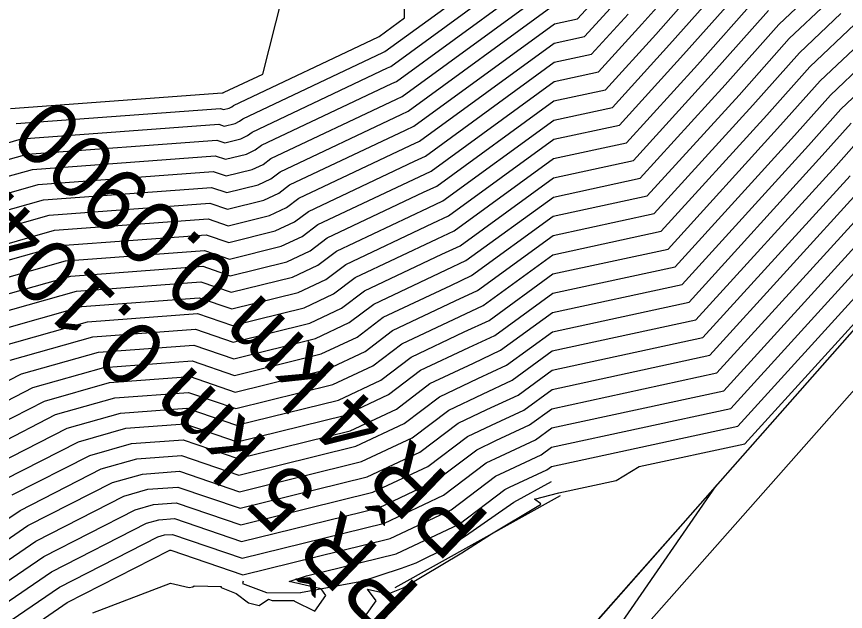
# Model space of a CAD drawing. Extents: x -549394 to -546608, y -1037055 to -1033629.
# Drawn here: x -547755.4 to -547637.4, y -1035785.5 to -1035700.8 of the extents above; entities that cross this region are included whole.
import ezdxf

# ---------------------------------------------------------------- set-up
doc = ezdxf.new("R2010")
doc.units = 0
for name, color, linetype in [('hlavni_vrst', 7, 'Continuous'), ('hrana_L', 7, 'Continuous'), ('norm_vrst', 7, 'Continuous'), ('x_popis_pricne_rezy_C111', 7, 'Continuous')]:
    doc.layers.add(name, color=color, linetype=linetype)

msp = doc.modelspace()

# ---------------------------------------------------------------- linework, layer by layer
at = {"layer": 'hlavni_vrst'}
for p, q in [((-547702.16, -1035707.89), (-547684.5, -1035695.02)), ((-547660.47, -1035706.19), (-547651.32, -1035695.89)), ((-547674.55, -1035703.62), (-547670.34, -1035698.99)), ((-547643.97, -1035705.93), (-547638.07, -1035700.36)), ((-547678.86, -1035704.55), (-547674.55, -1035703.62)), ((-547698.04, -1035718.53), (-547678.86, -1035704.55)), ((-547650.59, -1035713.39), (-547643.97, -1035705.93)), ((-547669.59, -1035716.23), (-547660.47, -1035706.19)), ((-547721.88, -1035717.22), (-547702.62, -1035708.1)), ((-547702.62, -1035708.1), (-547702.16, -1035707.89)), ((-547664.63, -1035728.84), (-547650.59, -1035713.39)), ((-547678.95, -1035718.25), (-547669.59, -1035716.23)), ((-547640.71, -1035720.58), (-547636.61, -1035715.96)), ((-547723.5, -1035718.18), (-547722.56, -1035717.74)), ((-547722.56, -1035717.74), (-547721.88, -1035717.22)), ((-547753.93, -1035720.37), (-547726.9, -1035718.36)), ((-547726.9, -1035718.36), (-547725.79, -1035718.74)), ((-547725.79, -1035718.74), (-547723.5, -1035718.18)), ((-547715.22, -1035726.64), (-547699.4, -1035719.16)), ((-547699.4, -1035719.16), (-547698.04, -1035718.53)), ((-547693.92, -1035729.16), (-547678.95, -1035718.25)), ((-547775.72, -1035726.53), (-547753.93, -1035720.37)), ((-547659.68, -1035741.45), (-547640.71, -1035720.58)), ((-547716.98, -1035727.98), (-547715.22, -1035726.64)), ((-547719.41, -1035729.12), (-547716.98, -1035727.98)), ((-547654.72, -1035754.06), (-547630.83, -1035727.78)), ((-547750.02, -1035731.22), (-547728.16, -1035729.59)), ((-547728.16, -1035729.59), (-547725.29, -1035730.58)), ((-547725.29, -1035730.58), (-547719.41, -1035729.12)), ((-547696.18, -1035730.22), (-547693.92, -1035729.16)), ((-547679.04, -1035731.96), (-547664.63, -1035728.84)), ((-547708.56, -1035736.07), (-547696.18, -1035730.22)), ((-547767.63, -1035736.2), (-547750.02, -1035731.22)), ((-547689.8, -1035739.8), (-547679.04, -1035731.96)), ((-547711.4, -1035738.23), (-547708.56, -1035736.07)), ((-547715.32, -1035740.07), (-547711.4, -1035738.23)), ((-547724.79, -1035742.41), (-547715.32, -1035740.07)), ((-547692.97, -1035741.27), (-547689.8, -1035739.8)), ((-547746.11, -1035742.06), (-547729.43, -1035740.83)), ((-547729.43, -1035740.83), (-547724.79, -1035742.41)), ((-547701.89, -1035745.5), (-547692.97, -1035741.27)), ((-547679.13, -1035745.66), (-547659.68, -1035741.45)), ((-547759.55, -1035745.87), (-547746.11, -1035742.06)), ((-547705.81, -1035748.47), (-547701.89, -1035745.5)), ((-547685.68, -1035750.43), (-547679.13, -1035745.66)), ((-547711.23, -1035751.02), (-547705.81, -1035748.47)), ((-547724.3, -1035754.25), (-547711.23, -1035751.02)), ((-547689.75, -1035752.33), (-547685.68, -1035750.43)), ((-547742.2, -1035752.91), (-547730.69, -1035752.06)), ((-547730.69, -1035752.06), (-547724.3, -1035754.25)), ((-547751.47, -1035755.54), (-547742.2, -1035752.91)), ((-547695.23, -1035754.92), (-547689.75, -1035752.33)), ((-547679.22, -1035759.36), (-547654.72, -1035754.06)), ((-547760.52, -1035760.16), (-547751.47, -1035755.54)), ((-547700.23, -1035758.72), (-547695.23, -1035754.92)), ((-547707.13, -1035761.96), (-547700.23, -1035758.72)), ((-547681.56, -1035761.07), (-547679.22, -1035759.36)), ((-547686.53, -1035763.38), (-547681.56, -1035761.07)), ((-547723.8, -1035766.08), (-547707.13, -1035761.96)), ((-547743.39, -1035765.2), (-547738.29, -1035763.76)), ((-547738.29, -1035763.76), (-547731.95, -1035763.29)), ((-547731.95, -1035763.29), (-547723.8, -1035766.08)), ((-547688.57, -1035764.35), (-547686.53, -1035763.38)), ((-547694.65, -1035768.96), (-547688.57, -1035764.35)), ((-547754.92, -1035771.1), (-547743.39, -1035765.2)), ((-547703.04, -1035772.91), (-547694.65, -1035768.96)), ((-547763.18, -1035776.76), (-547754.92, -1035771.1)), ((-547723.31, -1035777.91), (-547703.04, -1035772.91)), ((-547735.31, -1035774.87), (-547734.38, -1035774.61)), ((-547734.38, -1035774.61), (-547733.22, -1035774.52)), ((-547733.22, -1035774.52), (-547723.31, -1035777.91)), ((-547749.32, -1035782.04), (-547735.31, -1035774.87)), ((-547759.36, -1035788.91), (-547749.32, -1035782.04))]:
    msp.add_line(p, q, dxfattribs=at)
at = {"layer": 'hrana_L'}
for p, q in [((-547715.7, -1035835.54), (-547624.65, -1035732.28)), ((-547620.92, -1035736.65), (-547711.23, -1035838.83)), ((-547684.63, -1035769.93), (-547679.27, -1035766.98)), ((-547701.53, -1035782.09), (-547677.97, -1035768.98)), ((-547691.51, -1035774.72), (-547684.63, -1035769.93)), ((-547694.03, -1035776.33), (-547691.51, -1035774.72)), ((-547698.55, -1035778.56), (-547694.03, -1035776.33)), ((-547706.56, -1035781.28), (-547700.64, -1035779.32)), ((-547700.64, -1035779.32), (-547698.55, -1035778.56)), ((-547723.17, -1035781.18), (-547723.24, -1035781.51)), ((-547723.24, -1035781.51), (-547719.83, -1035782.79)), ((-547706.56, -1035781.28), (-547715.02, -1035782.83)), ((-547719.83, -1035782.79), (-547715.02, -1035782.83))]:
    msp.add_line(p, q, dxfattribs=at)
at = {"layer": 'norm_vrst'}
for p, q in [((-547700.17, -1035700.98), (-547699.62, -1035660.71)), ((-547666.39, -1035701.87), (-547655.74, -1035689.87)), ((-547720.38, -1035708.96), (-547715.97, -1035691.59)), ((-547664.42, -1035703.31), (-547654.27, -1035691.88)), ((-547701.34, -1035710.02), (-547678.78, -1035693.59)), ((-547662.44, -1035704.75), (-547652.8, -1035693.89)), ((-547700.52, -1035712.14), (-547678.8, -1035696.33)), ((-547675.54, -1035701.1), (-547672.32, -1035697.56)), ((-547658.49, -1035707.63), (-547649.85, -1035697.9)), ((-547646.91, -1035701.91), (-547642.08, -1035697.35)), ((-547702.99, -1035705.76), (-547692.33, -1035698)), ((-547699.69, -1035714.27), (-547678.82, -1035699.07)), ((-547645.44, -1035703.92), (-547640.07, -1035698.85)), ((-547656.52, -1035709.07), (-547648.38, -1035699.91)), ((-547703.81, -1035703.64), (-547700.17, -1035700.98)), ((-547678.84, -1035701.81), (-547675.54, -1035701.1)), ((-547673.56, -1035706.14), (-547668.37, -1035700.43)), ((-547698.87, -1035716.4), (-547678.84, -1035701.81)), ((-547672.56, -1035708.66), (-547666.39, -1035701.87)), ((-547654.54, -1035710.51), (-547646.91, -1035701.91)), ((-547642.5, -1035707.93), (-547636.07, -1035701.86)), ((-547724.54, -1035713.45), (-547703.91, -1035703.68)), ((-547703.91, -1035703.68), (-547703.81, -1035703.64)), ((-547671.57, -1035711.19), (-547664.42, -1035703.31)), ((-547641.03, -1035709.94), (-547634.06, -1035703.37)), ((-547670.58, -1035713.71), (-547662.44, -1035704.75)), ((-547652.56, -1035711.95), (-547645.44, -1035703.92)), ((-547639.55, -1035711.95), (-547632.06, -1035704.87)), ((-547723.21, -1035715.33), (-547703.26, -1035705.89)), ((-547703.26, -1035705.89), (-547702.99, -1035705.76)), ((-547678.88, -1035707.29), (-547673.56, -1035706.14)), ((-547697.22, -1035720.65), (-547678.88, -1035707.29)), ((-547638.08, -1035713.96), (-547630.05, -1035706.38)), ((-547668.6, -1035718.75), (-547658.49, -1035707.63)), ((-547648.61, -1035714.82), (-547642.5, -1035707.93)), ((-547725.87, -1035711.56), (-547720.38, -1035708.96)), ((-547678.89, -1035710.03), (-547672.56, -1035708.66)), ((-547667.61, -1035721.27), (-547656.52, -1035709.07)), ((-547720.54, -1035719.1), (-547701.98, -1035710.31)), ((-547701.98, -1035710.31), (-547701.34, -1035710.02)), ((-547696.39, -1035722.78), (-547678.89, -1035710.03)), ((-547666.62, -1035723.8), (-547654.54, -1035710.51)), ((-547646.64, -1035716.26), (-547641.03, -1035709.94)), ((-547756.28, -1035713.86), (-547726.14, -1035711.62)), ((-547726.14, -1035711.62), (-547726.08, -1035711.64)), ((-547726.08, -1035711.64), (-547725.96, -1035711.61)), ((-547725.96, -1035711.61), (-547725.91, -1035711.59)), ((-547725.91, -1035711.59), (-547725.87, -1035711.56)), ((-547678.91, -1035712.77), (-547671.57, -1035711.19)), ((-547665.63, -1035726.32), (-547652.56, -1035711.95)), ((-547644.66, -1035717.7), (-547639.55, -1035711.95)), ((-547719.21, -1035720.99), (-547701.33, -1035712.53)), ((-547701.33, -1035712.53), (-547700.52, -1035712.14)), ((-547695.57, -1035724.91), (-547678.91, -1035712.77)), ((-547755.5, -1035716.03), (-547726.4, -1035713.87)), ((-547726.4, -1035713.87), (-547725.98, -1035714.01)), ((-547725.98, -1035714.01), (-547725.14, -1035713.8)), ((-547725.14, -1035713.8), (-547724.79, -1035713.64)), ((-547724.79, -1035713.64), (-547724.54, -1035713.45)), ((-547700.69, -1035714.74), (-547699.69, -1035714.27)), ((-547678.93, -1035715.51), (-547670.58, -1035713.71)), ((-547642.69, -1035719.14), (-547638.08, -1035713.96)), ((-547723.68, -1035715.69), (-547723.21, -1035715.33)), ((-547717.88, -1035722.87), (-547700.69, -1035714.74)), ((-547694.75, -1035727.03), (-547678.93, -1035715.51)), ((-547663.64, -1035731.36), (-547648.61, -1035714.82)), ((-547754.72, -1035718.2), (-547726.65, -1035716.11)), ((-547726.65, -1035716.11), (-547725.88, -1035716.38)), ((-547725.88, -1035716.38), (-547724.32, -1035715.99)), ((-547724.32, -1035715.99), (-547723.68, -1035715.69)), ((-547700.05, -1035716.95), (-547698.87, -1035716.4)), ((-547662.65, -1035733.89), (-547646.64, -1035716.26)), ((-547716.55, -1035724.76), (-547700.05, -1035716.95)), ((-547661.66, -1035736.41), (-547644.66, -1035717.7)), ((-547638.74, -1035722.02), (-547635.14, -1035717.97)), ((-547777.33, -1035724.59), (-547754.72, -1035718.2)), ((-547721.44, -1035719.78), (-547720.54, -1035719.1)), ((-547678.97, -1035720.99), (-547668.6, -1035718.75)), ((-547660.67, -1035738.93), (-547642.69, -1035719.14)), ((-547722.69, -1035720.37), (-547721.44, -1035719.78)), ((-547753.15, -1035722.54), (-547727.15, -1035720.61)), ((-547727.15, -1035720.61), (-547725.69, -1035721.11)), ((-547725.69, -1035721.11), (-547722.69, -1035720.37)), ((-547720.33, -1035721.83), (-547719.21, -1035720.99)), ((-547713.88, -1035728.53), (-547698.76, -1035721.37)), ((-547698.76, -1035721.37), (-547697.22, -1035720.65)), ((-547693.1, -1035731.29), (-547678.97, -1035720.99)), ((-547678.98, -1035723.74), (-547667.61, -1035721.27)), ((-547774.1, -1035728.46), (-547753.15, -1035722.54)), ((-547725.59, -1035723.48), (-547721.87, -1035722.56)), ((-547721.87, -1035722.56), (-547720.33, -1035721.83)), ((-547658.69, -1035743.97), (-547638.74, -1035722.02)), ((-547752.37, -1035724.71), (-547727.41, -1035722.85)), ((-547727.41, -1035722.85), (-547725.59, -1035723.48)), ((-547719.21, -1035723.88), (-547717.88, -1035722.87)), ((-547712.55, -1035730.41), (-547698.12, -1035723.58)), ((-547698.12, -1035723.58), (-547696.39, -1035722.78)), ((-547692.27, -1035733.41), (-547678.98, -1035723.74)), ((-547679, -1035726.48), (-547666.62, -1035723.8)), ((-547657.7, -1035746.5), (-547636.76, -1035723.46)), ((-547772.48, -1035730.39), (-547752.37, -1035724.71)), ((-547725.49, -1035725.84), (-547721.05, -1035724.75)), ((-547721.05, -1035724.75), (-547719.21, -1035723.88)), ((-547718.09, -1035725.93), (-547716.55, -1035724.76)), ((-547697.47, -1035725.79), (-547695.57, -1035724.91)), ((-547656.7, -1035749.02), (-547634.78, -1035724.9)), ((-547751.59, -1035726.88), (-547727.66, -1035725.1)), ((-547727.66, -1035725.1), (-547725.49, -1035725.84)), ((-547720.23, -1035726.94), (-547718.09, -1035725.93)), ((-547711.22, -1035732.3), (-547697.47, -1035725.79)), ((-547770.87, -1035732.33), (-547751.59, -1035726.88)), ((-547750.8, -1035729.05), (-547727.91, -1035727.35)), ((-547727.91, -1035727.35), (-547725.39, -1035728.21)), ((-547725.39, -1035728.21), (-547720.23, -1035726.94)), ((-547696.83, -1035728), (-547694.75, -1035727.03)), ((-547691.45, -1035735.54), (-547679, -1035726.48)), ((-547679.02, -1035729.22), (-547665.63, -1035726.32)), ((-547655.71, -1035751.54), (-547632.81, -1035726.34)), ((-547715.86, -1035730.03), (-547713.88, -1035728.53)), ((-547709.89, -1035734.18), (-547696.83, -1035728)), ((-547769.25, -1035734.26), (-547750.8, -1035729.05)), ((-547690.63, -1035737.67), (-547679.02, -1035729.22)), ((-547653.73, -1035756.58), (-547628.86, -1035729.21)), ((-547718.59, -1035731.31), (-547715.86, -1035730.03)), ((-547714.74, -1035732.08), (-547712.55, -1035730.41)), ((-547652.74, -1035759.11), (-547626.88, -1035730.65)), ((-547749.24, -1035733.39), (-547728.42, -1035731.84)), ((-547728.42, -1035731.84), (-547725.19, -1035732.94)), ((-547725.19, -1035732.94), (-547718.59, -1035731.31)), ((-547717.77, -1035733.5), (-547714.74, -1035732.08)), ((-547695.54, -1035732.43), (-547693.1, -1035731.29)), ((-547679.06, -1035734.7), (-547663.64, -1035731.36)), ((-547651.75, -1035761.63), (-547624.91, -1035732.09)), ((-547713.63, -1035734.13), (-547711.22, -1035732.3)), ((-547707.22, -1035737.95), (-547695.54, -1035732.43)), ((-547766.02, -1035738.13), (-547749.24, -1035733.39)), ((-547748.46, -1035735.56), (-547728.67, -1035734.09)), ((-547728.67, -1035734.09), (-547725.09, -1035735.31)), ((-547725.09, -1035735.31), (-547717.77, -1035733.5)), ((-547716.96, -1035735.69), (-547713.63, -1035734.13)), ((-547712.51, -1035736.18), (-547709.89, -1035734.18)), ((-547694.9, -1035734.64), (-547692.27, -1035733.41)), ((-547679.07, -1035737.44), (-547662.65, -1035733.89)), ((-547764.4, -1035740.06), (-547748.46, -1035735.56)), ((-547705.89, -1035739.84), (-547694.9, -1035734.64)), ((-547694.25, -1035736.85), (-547691.45, -1035735.54)), ((-547688.98, -1035741.92), (-547679.06, -1035734.7)), ((-547747.68, -1035737.73), (-547728.92, -1035736.33)), ((-547728.92, -1035736.33), (-547724.99, -1035737.68)), ((-547724.99, -1035737.68), (-547716.96, -1035735.69)), ((-547716.14, -1035737.88), (-547712.51, -1035736.18)), ((-547704.56, -1035741.73), (-547694.25, -1035736.85)), ((-547679.09, -1035740.18), (-547661.66, -1035736.41)), ((-547762.79, -1035742), (-547747.68, -1035737.73)), ((-547724.89, -1035740.04), (-547716.14, -1035737.88)), ((-547710.28, -1035740.28), (-547707.22, -1035737.95)), ((-547693.61, -1035739.06), (-547690.63, -1035737.67)), ((-547688.15, -1035744.05), (-547679.07, -1035737.44)), ((-547746.89, -1035739.89), (-547729.17, -1035738.58)), ((-547729.17, -1035738.58), (-547724.89, -1035740.04)), ((-547703.23, -1035743.61), (-547693.61, -1035739.06)), ((-547679.11, -1035742.92), (-547660.67, -1035738.93)), ((-547761.17, -1035743.93), (-547746.89, -1035739.89)), ((-547714.5, -1035742.26), (-547710.28, -1035740.28)), ((-547709.16, -1035742.32), (-547705.89, -1035739.84)), ((-547687.33, -1035746.18), (-547679.09, -1035740.18)), ((-547724.69, -1035744.78), (-547714.5, -1035742.26)), ((-547713.68, -1035744.45), (-547709.16, -1035742.32)), ((-547708.05, -1035744.37), (-547704.56, -1035741.73)), ((-547692.32, -1035743.48), (-547688.98, -1035741.92)), ((-547745.33, -1035744.23), (-547729.68, -1035743.07)), ((-547729.68, -1035743.07), (-547724.69, -1035744.78)), ((-547706.93, -1035746.42), (-547703.23, -1035743.61)), ((-547700.56, -1035747.38), (-547692.32, -1035743.48)), ((-547686.51, -1035748.3), (-547679.11, -1035742.92)), ((-547757.94, -1035747.8), (-547745.33, -1035744.23)), ((-547724.6, -1035747.14), (-547713.68, -1035744.45)), ((-547712.86, -1035746.64), (-547708.05, -1035744.37)), ((-547691.68, -1035745.69), (-547688.15, -1035744.05)), ((-547679.15, -1035748.4), (-547658.69, -1035743.97)), ((-547744.55, -1035746.4), (-547729.93, -1035745.32)), ((-547729.93, -1035745.32), (-547724.6, -1035747.14)), ((-547699.23, -1035749.27), (-547691.68, -1035745.69)), ((-547691.04, -1035747.91), (-547687.33, -1035746.18)), ((-547756.32, -1035749.73), (-547744.55, -1035746.4)), ((-547724.5, -1035749.51), (-547712.86, -1035746.64)), ((-547712.04, -1035748.83), (-547706.93, -1035746.42)), ((-547704.7, -1035750.52), (-547700.56, -1035747.38)), ((-547679.17, -1035751.14), (-547657.7, -1035746.5)), ((-547754.7, -1035751.67), (-547743.76, -1035748.57)), ((-547743.76, -1035748.57), (-547730.19, -1035747.57)), ((-547730.19, -1035747.57), (-547724.5, -1035749.51)), ((-547697.9, -1035751.15), (-547691.04, -1035747.91)), ((-547690.39, -1035750.12), (-547686.51, -1035748.3)), ((-547684.86, -1035752.56), (-547679.15, -1035748.4)), ((-547742.98, -1035750.74), (-547730.44, -1035749.81)), ((-547730.44, -1035749.81), (-547724.4, -1035751.88)), ((-547724.4, -1035751.88), (-547712.04, -1035748.83)), ((-547703.58, -1035752.57), (-547699.23, -1035749.27)), ((-547679.18, -1035753.88), (-547656.7, -1035749.02)), ((-547753.09, -1035753.6), (-547742.98, -1035750.74)), ((-547710.41, -1035753.2), (-547704.7, -1035750.52)), ((-547696.57, -1035753.04), (-547690.39, -1035750.12)), ((-547762.76, -1035755.78), (-547754.7, -1035751.67)), ((-547702.46, -1035754.62), (-547697.9, -1035751.15)), ((-547684.03, -1035754.69), (-547679.17, -1035751.14)), ((-547679.2, -1035756.62), (-547655.71, -1035751.54)), ((-547724.2, -1035756.61), (-547710.41, -1035753.2)), ((-547709.59, -1035755.39), (-547703.58, -1035752.57)), ((-547701.35, -1035756.67), (-547696.57, -1035753.04)), ((-547689.11, -1035754.54), (-547684.86, -1035752.56)), ((-547761.64, -1035757.97), (-547753.09, -1035753.6)), ((-547741.42, -1035755.08), (-547730.94, -1035754.31)), ((-547730.94, -1035754.31), (-547724.2, -1035756.61)), ((-547693.9, -1035756.81), (-547689.11, -1035754.54)), ((-547683.21, -1035756.81), (-547679.18, -1035753.88)), ((-547749.86, -1035757.47), (-547741.42, -1035755.08)), ((-547724.1, -1035758.98), (-547709.59, -1035755.39)), ((-547708.77, -1035757.58), (-547702.46, -1035754.62)), ((-547688.46, -1035756.75), (-547684.03, -1035754.69)), ((-547740.63, -1035757.25), (-547731.2, -1035756.55)), ((-547731.2, -1035756.55), (-547724.1, -1035758.98)), ((-547707.95, -1035759.77), (-547701.35, -1035756.67)), ((-547699.11, -1035760.77), (-547693.9, -1035756.81)), ((-547692.57, -1035758.69), (-547688.46, -1035756.75)), ((-547687.82, -1035758.96), (-547683.21, -1035756.81)), ((-547682.39, -1035758.94), (-547679.2, -1035756.62)), ((-547679.24, -1035762.1), (-547653.73, -1035756.58)), ((-547759.4, -1035762.35), (-547749.86, -1035757.47)), ((-547748.24, -1035759.4), (-547740.63, -1035757.25)), ((-547724, -1035761.35), (-547708.77, -1035757.58)), ((-547739.85, -1035759.42), (-547731.45, -1035758.8)), ((-547731.45, -1035758.8), (-547724, -1035761.35)), ((-547698, -1035762.81), (-547692.57, -1035758.69)), ((-547691.24, -1035760.58), (-547687.82, -1035758.96)), ((-547687.18, -1035761.17), (-547682.39, -1035758.94)), ((-547679.26, -1035764.84), (-547652.74, -1035759.11)), ((-547758.28, -1035764.53), (-547748.24, -1035759.4)), ((-547746.62, -1035761.34), (-547739.85, -1035759.42)), ((-547723.9, -1035763.71), (-547707.95, -1035759.77)), ((-547757.16, -1035766.72), (-547746.62, -1035761.34)), ((-547745.01, -1035763.27), (-547739.07, -1035761.59)), ((-547739.07, -1035761.59), (-547731.7, -1035761.04)), ((-547731.7, -1035761.04), (-547723.9, -1035763.71)), ((-547706.31, -1035764.15), (-547699.11, -1035760.77)), ((-547696.88, -1035764.86), (-547691.24, -1035760.58)), ((-547689.91, -1035762.46), (-547687.18, -1035761.17)), ((-547666.79, -1035764.88), (-547651.75, -1035761.63)), ((-547705.49, -1035766.34), (-547698, -1035762.81)), ((-547695.76, -1035766.91), (-547689.91, -1035762.46)), ((-547680.74, -1035763.19), (-547679.24, -1035762.1)), ((-547756.04, -1035768.91), (-547745.01, -1035763.27)), ((-547685.89, -1035765.6), (-547680.74, -1035763.19)), ((-547723.7, -1035768.45), (-547706.31, -1035764.15)), ((-547704.68, -1035768.53), (-547696.88, -1035764.86)), ((-547679.91, -1035765.32), (-547679.26, -1035764.84)), ((-547670.04, -1035766.86), (-547666.79, -1035764.88)), ((-547741.78, -1035767.14), (-547737.51, -1035765.93)), ((-547737.51, -1035765.93), (-547732.21, -1035765.54)), ((-547732.21, -1035765.54), (-547723.7, -1035768.45)), ((-547723.6, -1035770.81), (-547705.49, -1035766.34)), ((-547693.53, -1035771.01), (-547687.24, -1035766.23)), ((-547687.24, -1035766.23), (-547685.89, -1035765.6)), ((-547685.25, -1035767.81), (-547679.91, -1035765.32)), ((-547753.8, -1035773.28), (-547741.78, -1035767.14)), ((-547703.86, -1035770.72), (-547695.76, -1035766.91)), ((-547678.21, -1035768.61), (-547670.04, -1035766.86)), ((-547740.16, -1035769.07), (-547736.72, -1035768.1)), ((-547736.72, -1035768.1), (-547732.46, -1035767.78)), ((-547732.46, -1035767.78), (-547723.6, -1035770.81)), ((-547723.51, -1035773.18), (-547704.68, -1035768.53)), ((-547692.41, -1035773.06), (-547685.91, -1035768.12)), ((-547685.91, -1035768.12), (-547685.25, -1035767.81)), ((-547655.8, -1035767.61), (-547684.83, -1035800.33)), ((-547681.67, -1035769.51), (-547678.21, -1035768.61)), ((-547669.24, -1035787.06), (-547655.8, -1035767.61)), ((-547752.68, -1035775.47), (-547740.16, -1035769.07)), ((-547680.79, -1035770.18), (-547681.67, -1035769.51)), ((-547751.56, -1035777.66), (-547738.54, -1035771.01)), ((-547738.54, -1035771.01), (-547735.94, -1035770.27)), ((-547735.94, -1035770.27), (-547732.71, -1035770.03)), ((-547732.71, -1035770.03), (-547723.51, -1035773.18)), ((-547723.41, -1035775.55), (-547703.86, -1035770.72)), ((-547702.22, -1035775.1), (-547693.53, -1035771.01)), ((-547687.79, -1035774.44), (-547680.84, -1035770.29)), ((-547680.84, -1035770.29), (-547680.79, -1035770.18)), ((-547762.42, -1035779.19), (-547753.8, -1035773.28)), ((-547750.44, -1035779.85), (-547736.93, -1035772.94)), ((-547736.93, -1035772.94), (-547735.16, -1035772.44)), ((-547735.16, -1035772.44), (-547732.96, -1035772.28)), ((-547732.96, -1035772.28), (-547723.41, -1035775.55)), ((-547701.4, -1035777.28), (-547692.41, -1035773.06)), ((-547692.02, -1035777.15), (-547687.79, -1035774.44)), ((-547761.65, -1035781.62), (-547752.68, -1035775.47)), ((-547723.21, -1035780.28), (-547702.22, -1035775.1)), ((-547748.2, -1035784.22), (-547733.69, -1035776.81)), ((-547733.69, -1035776.81), (-547733.59, -1035776.78)), ((-547733.59, -1035776.78), (-547733.47, -1035776.77)), ((-547733.47, -1035776.77), (-547723.21, -1035780.28)), ((-547760.89, -1035784.05), (-547751.56, -1035777.66)), ((-547714.16, -1035780.44), (-547701.4, -1035777.28)), ((-547700.36, -1035782.13), (-547692.02, -1035777.15)), ((-547760.12, -1035786.48), (-547750.44, -1035779.85)), ((-547716.61, -1035781.22), (-547714.16, -1035780.44)), ((-547744.55, -1035785.71), (-547733.49, -1035781.49)), ((-547733.49, -1035781.49), (-547730.87, -1035782.11)), ((-547712.06, -1035782.29), (-547716.61, -1035781.22)), ((-547730.87, -1035782.11), (-547730.34, -1035781.98)), ((-547730.34, -1035781.98), (-547730.12, -1035781.87)), ((-547730.12, -1035781.87), (-547726.26, -1035781.93)), ((-547726.29, -1035782.08), (-547726.26, -1035781.93)), ((-547726.29, -1035782.08), (-547724.18, -1035782.95)), ((-547711.38, -1035783.22), (-547712.06, -1035782.29)), ((-547704.23, -1035783.98), (-547705.44, -1035782.34)), ((-547705.44, -1035782.34), (-547702.52, -1035783)), ((-547702.52, -1035783), (-547700.36, -1035782.13)), ((-547724.18, -1035782.95), (-547722.38, -1035784.26)), ((-547720.87, -1035784.66), (-547719.54, -1035783.74)), ((-547719.54, -1035783.74), (-547719.04, -1035783.93)), ((-547719.04, -1035783.93), (-547715.96, -1035783.93)), ((-547715.96, -1035783.93), (-547715.87, -1035784.03)), ((-547715.87, -1035784.03), (-547712.97, -1035785.47)), ((-547712.97, -1035785.47), (-547711.38, -1035783.22)), ((-547708.95, -1035790.65), (-547704.23, -1035783.98)), ((-547758.6, -1035791.34), (-547748.2, -1035784.22)), ((-547722.38, -1035784.26), (-547720.87, -1035784.66))]:
    msp.add_line(p, q, dxfattribs=at)

# ---------------------------------------------------------------- texts
at = {"layer": 'x_popis_pricne_rezy_C111'}
for s, p in [('PŘ 4 km 0.0900', (-547687.73, -1035772.15)), ('PŘ 5 km 0.1042', (-547697.6, -1035782.4))]:
    msp.add_text(s, height=9.0627, rotation=136.0787, dxfattribs=at).set_placement(p)

doc.saveas('drawing.dxf')
